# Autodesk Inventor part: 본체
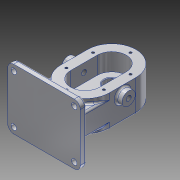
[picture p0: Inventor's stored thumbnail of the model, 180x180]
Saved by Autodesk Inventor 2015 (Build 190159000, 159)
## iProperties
Created: 2020-09
Part Number: 본체
Material: 알루미늄 6061
Document SubType Name: Modeling
Designer: LINEART-SSD.D4.16.04
Density: 2.7 g/cm^3
Appearance: 알루미늄 - 평지
Mass: 1438.7 g
Surface Area: 781.105 cm^2
Volume: 532.85 cm^3
Author: LINEART-SSD.D4.16.04
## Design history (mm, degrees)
sketch "스케치1"
  geometry: L1 (0, 0)-(0, 44); L2 (-40, 0)-(-40, 44); L3 (40, 44)-(40, 0); L4 (0, 0)-(0, 44); L5 (-24, 0)-(-24, 44); L6 (24, 44)-(24, 0); A1 r 40 centre (0, 0) between (-40, 0) and (40, 0); A2 r 40 centre (0, 44) between (40, 44) and (-40, 44); A3 r 24 centre (0, 0) between (-24, 0) and (24, 0); A4 r 24 centre (0, 44) between (24, 44) and (-24, 44); 2 further points
  constraints: 16 end point, 8 point on circle, 8 tangent, 4 centre point, 2 midpoint, 2 parallel, 2 vertical
  dimensions: "d0" = 44 distance of L1.start L1.end; "d1" = 40 radius of A2; "d2" = 24 radius of A4
extrude "돌출1" new body sketch "스케치1" distance "d3" = 53; taper "d4" = 0 deg
extrude "돌출2" join sketch "스케치1" distance "d5" = 24; taper "d6" = 0 deg
sketch "스케치2"
  geometry: C1 r 12.5 at (0, 0); C2 r 12.5 at (0, 44); A1 r 40 centre (0, 44) between (40, 44) and (-40, 44) reference; 1 further point
  constraints: 2 centre point, 2 coincident
  dimensions: "d7" = 25 diameter of C1; "d8" = 25 diameter of C2
extrude "돌출3" cut sketch "스케치2" distance "d9" = 15; taper "d10" = 0 deg
sketch "스케치3"
  geometry: C1 r 8.5 at (0, 0); 1 further point
  constraints: 1 centre point
  dimensions: "d11" = 17 diameter of C1
sketch "스케치4"
  geometry: C1 r 19 at (0, 44); A1 r 40 centre (0, 44) between (40, 44) and (-40, 44) reference; 1 further point
  constraints: 1 centre point, 1 coincident
  dimensions: "d12" = 38 diameter of C1
extrude "돌출4" join sketch "스케치4" distance "d13" = 17; taper "d14" = 0 deg
sketch "스케치5"
  geometry: C1 r 14 at (0, 0); 1 further point
  constraints: 1 centre point
  dimensions: "d15" = 28 diameter of C1
extrude "돌출5" cut sketch "스케치5" distance "d16" = 7.3; taper "d17" = 0 deg
extrude "돌출6" cut sketch "스케치3" stored distance "d18" = 7.3; taper "d19" = 0 deg
sketch "스케치7"
  geometry: L1 (-53, 0)-(-53, 44) reference; L2 (0, 0)-(-53, 0) reference; L3 (0, 44)-(0, 0) reference; L4 (0, 84)-(-53, 84) reference; L5 (0, -40)-(-53, -40) reference; L6 (-53, 44)-(-53, 0) reference; L7 (-53, 22)-(-39, 22); C1 r 11 at (-39, 22)
  constraints: 2 end point, 1 centre point, 1 coincident, 1 horizontal, 1 midpoint
  dimensions: "d20" = 14 distance of L7.start L7.end; "d21" = 22 diameter of C1
extrude "돌출7" join sketch "스케치7" distance "d22" = 10; taper "d23" = 0 deg
node "작업 평면1"
sketch "스케치8"
  geometry: L1 (-40, 0)-(40, 0) reference; L2 (40, 0)-(40, 53) reference; L3 (40, 53)-(-40, 53) reference; L4 (-40, 0)-(-40, 53) reference; L5 (-19, -17)-(19, -17) reference; L6 (0, -17)-(-60, -17); L7 (-60, -17)-(60, -17); L8 (60, -17)-(60, 83); L9 (60, 83)-(-60, 83); L10 (-60, 83)-(-60, -17); 1 further point
  constraints: 10 end point, 2 parallel, 1 horizontal, 1 midpoint, 1 perpendicular, 1 point on line
  dimensions: "d25" = 60 distance of L6.start L6.end; "d26" = 120 distance of L9.end L8.end; "d27" = 100 distance of L8.end L7.end
extrude "돌출8" join sketch "스케치8" distance "d28" = 10; taper "d29" = 0 deg
node "작업 평면2"
sketch "스케치9"
  geometry: L1 (60, -68)-(-60, -68) reference; L2 (-60, -68)-(-60, -58) reference; L3 (60, -58)-(-60, -58) reference; L4 (60, -68)-(60, -58) reference; L5 (60, -58)-(-60, -58) reference; L6 (0, -58)-(-40, -58); L7 (0, -58)-(40, -58); L8 (40, -58)-(40, 0); L9 (-40, -58)-(-40, 0); L10 (-40, 0)-(-17.911, -27.515); L11 (-17.911, -27.515)-(15.056, -27.515); L12 (15.056, -27.515)-(40, 0); A1 r 40 centre (0, 0) between (-40, 0) and (40, 0) reference; 1 further point
  constraints: 14 end point, 2 point on line, 1 midpoint, 1 perpendicular
  dimensions: "d30" = 40 distance of L6.start L6.end; "d31" = 40 distance of L6.start L7.end; "d32" = 47.8057 deg angle of L3 L12; "d33" = 51.2428 deg angle of L3 L10; "d34" = 30.48466 distance from line of L3.start L11
extrude "돌출9" join sketch "스케치9" stored distance "d35" = 37; taper "d36" = 0 deg
hole "구멍1" diameter "d39" = 8.376; stored, may be unused: countersink angle "d43" = 90 deg, drill point angle "d45" = 118 deg; dims "d40" = 40, "d41" = 4, "d42" = 2, "d44" = 47.3, "d101" = 10, "d102" = 10
hole "구멍2" diameter "d48" = 8.376; stored, may be unused: countersink angle "d52" = 90 deg, drill point angle "d54" = 118 deg; dims "d49" = 50, "d50" = 4, "d51" = 2, "d53" = 27.3, "d103" = 10, "d104" = 10
sketch "스케치11" dims "d57" = 31
  geometry: L1 (0, 0)-(0, 44); L2 (0, 0)-(0, -31); 1 further point
  constraints: 6 end point, 2 vertical, 1 coincident, 1 midpoint, 1 vertical alignment, 2 other
hole "구멍3" sketch "스케치11" at (0, -31) diameter "d58" = 4.134; stored, may be unused: countersink angle "d62" = 90 deg, drill point angle "d64" = 118 deg; dims "d59" = 10, "d60" = 4, "d61" = 2, "d63" = 12
sketch "스케치12"
  geometry: L1 (0, -31)-(0, 75); L2 (0, 75)-(0, 44); L3 (0, 44)-(31, 44); L4 (0, 44)-(-31, 44); L5 (0, 0)-(31, 0); L6 (0, 0)-(-31, 0); C1 r 2.067 at (0, -31) reference; A1 r 31 centre (0, 44) between (31, 44) and (-31, 44); A2 r 31 centre (0, 0) between (31, 0) and (-31, 0); 1 further point
  constraints: 12 end point, 4 horizontal, 4 point on circle, 2 centre point, 2 coincident, 1 point on line, 1 vertical
  dimensions: "d65" = 106 distance of L1.start L1.end; "d66" = 31 distance of L1.end L2.end; "d67" = 31 radius of A1; "d68" = 31 radius of A2
hole "구멍4" sketch "스케치12" at (-31, 44), (-31, 0), (31, 0), (31, 44), (0, 75) diameter "d69" = 4.134; stored, may be unused: countersink angle "d73" = 90 deg, drill point angle "d75" = 118 deg; dims "d70" = 10, "d71" = 4, "d72" = 2, "d74" = 12
sketch "스케치13"
  geometry: L1 (60, 17)-(-60, 17) reference; L2 (-60, -83)-(60, -83) reference; L3 (-60, 17)-(-50, 17); L4 (-50, 17)-(-50, 7); L5 (-60, -83)-(-50, -83); L6 (-50, -83)-(-50, -73); L7 (-50, -73)-(-60, -73); L8 (-60, -73)-(-60, -83); C1 r 4.5 at (-50, 7); C2 r 4.5 at (-50, -73); 1 further point
  constraints: 12 end point, 2 centre point, 2 parallel, 2 perpendicular, 1 coincident, 1 horizontal, 1 point on line
  dimensions: "d76" = 10 distance of L1.end L3.end; "d77" = 10 distance of L3.end L4.end; "d79" = 9 diameter of C1; "d80" = 10 distance from line of C1.centre L1; "d81" = 0 distance from line of C1.centre L4; "d85" = 10 distance of L7.end L6.end; "d86" = 10 distance of L6.end L5.end; "d87" = 9 diameter of C2
extrude "돌출10" cut sketch "스케치13" stored distance "d82" = 37; taper "d83" = 0 deg
fillet "모깎기1" dims "d84" = 10
extrude "돌출11" cut sketch "스케치13" stored distance "d88" = 37; taper "d89" = 0 deg
node "작업 평면4"
fillet "모깎기2" dims "d90" = 10
chamfer "모따기1" distance "d91" = 1; stored, may be unused: second distance "d92" = 2, angle "d93" = 45 deg
chamfer "모따기2" distance "d94" = 0.7; stored, may be unused: second distance "d95" = 2, angle "d96" = 45 deg
fillet "모깎기3" dims "d97" = 3
fillet "모깎기4" dims "d98" = 0.5
fillet "모깎기6" dims "d100" = 3
sketch "스케치16"
  geometry: L1 (-50, -83)-(50, -83) reference; L2 (-60, 7)-(-60, -73) reference; 2 further points
  constraints: 1 other
  dimensions: "d105" = 12 distance from line of L1 point (0, -71); "d106" = 60 distance from line of L2 point (0, -71)
feature "엠보싱1" sketch "스케치16" dims "d0" = 44, "d1" = 40, "d2" = 24, "d107" = 0.5, "d108" = 0
node "솔리드1"
mirror "대칭1"
mirror "대칭2"
node "투영된 루프1"
other parameters: "d24" = -68
